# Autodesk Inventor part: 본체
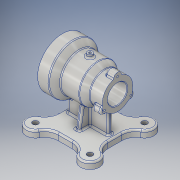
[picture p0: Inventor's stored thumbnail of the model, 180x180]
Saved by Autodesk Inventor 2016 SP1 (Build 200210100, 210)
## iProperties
Created: 2017-03
Part Number: 본체
Material: 알루미늄 6061
Document SubType Name: Modeling
Designer: Administrator
Density: 2.7 g/cm^3
Appearance: 알루미늄 - 평지
Mass: 958.762 g
Surface Area: 833.206 cm^2
Volume: 355.097 cm^3
Author: Administrator
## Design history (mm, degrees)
sketch "스케치1"
  geometry: L1 (45, 45)-(-45, 45); L2 (-45, 45)-(-45, -45); L3 (-45, -45)-(45, -45); L4 (45, -45)-(45, 45); L5 (45, 45)-(-45, -45); L6 (-45, 45)-(45, -45); C1 r 70 at (0, 0); 1 further point
  constraints: 12 end point, 4 midpoint, 2 parallel, 1 centre point, 1 horizontal, 1 perpendicular
  dimensions: "d0" = 90 distance of L3.end L2.end; "d1" = 90 distance of L2.end L1.end; "d2" = 140 diameter of C1
extrude "돌출1" new body sketch "스케치1" distance "d3" = 12; taper "d4" = 0 deg
sketch "스케치5"
  geometry: L1 (0, 0)-(49.497, -49.497); L2 (0, 0)-(49.497, 49.497); L3 (70, 0)-(-70, 0); L4 (0, -70)-(0, 70); C1 r 17 at (49.497, -49.497); C2 r 17 at (-49.497, -49.497); C3 r 17 at (49.497, 49.497); C4 r 17 at (-49.497, 49.497); A1 r 70 centre (0, 0) between (49.497, -49.497) and (49.497, 49.497); 1 further point
  constraints: 8 end point, 6 point on circle, 5 centre point, 3 symmetric about line, 2 coincident, 1 horizontal, 1 vertical, 3 other
  dimensions: "d14" = 140 diameter of A1; "d15" = 45 deg angle of L3 L1; "d16" = 45 deg angle of L2 L3; "d17" = 17 radius of C1
extrude "돌출2" join sketch "스케치5" distance "d19" = 12; taper "d20" = 0 deg
fillet "모깎기1" dims "d21" = 25
sketch "스케치6"
  geometry: L1 (45, -12.842)-(45, 12.842) reference; L2 (12.842, 45)-(-12.842, 45) reference; L3 (-45, 12.842)-(-45, -12.842) reference; L4 (-12.842, -45)-(12.842, -45) reference; C1 r 5 at (49.497, 49.497); C2 r 5 at (49.497, -49.497); C3 r 5 at (-49.497, -49.497); C4 r 5 at (-49.497, 49.497); A1 r 25 centre (70, 12.842) between (57.796, 34.661) and (45, 12.842) reference; A2 r 17 centre (49.497, 49.497) between (57.796, 34.661) and (34.661, 57.796) reference; A3 r 25 centre (12.842, 70) between (12.842, 45) and (34.661, 57.796) reference; A4 r 25 centre (-12.842, 70) between (-34.661, 57.796) and (-12.842, 45) reference; A5 r 17 centre (-49.497, 49.497) between (-34.661, 57.796) and (-57.796, 34.661) reference; A6 r 25 centre (-70, 12.842) between (-45, 12.842) and (-57.796, 34.661) reference; A7 r 25 centre (-70, -12.842) between (-57.796, -34.661) and (-45, -12.842) reference; A8 r 17 centre (-49.497, -49.497) between (-57.796, -34.661) and (-34.661, -57.796) reference; A9 r 25 centre (-12.842, -70) between (-12.842, -45) and (-34.661, -57.796) reference; A10 r 25 centre (12.842, -70) between (34.661, -57.796) and (12.842, -45) reference; A11 r 17 centre (49.497, -49.497) between (34.661, -57.796) and (57.796, -34.661) reference; A12 r 25 centre (70, -12.842) between (45, -12.842) and (57.796, -34.661) reference; 1 further point
  constraints: 4 centre point, 4 coincident, 3 equal radius
  dimensions: "d22" = 10 diameter of C1
extrude "돌출3" cut sketch "스케치6" stored distance "d23" = 12; taper "d24" = 0 deg
fillet "모깎기2" dims "d25" = 3
sketch "스케치7"
  geometry: L1 (-50, 82)-(50, 82); L2 (12.842, 0)-(-12.842, 0) reference; L3 (27, 109.5)-(15, 116.599); L4 (15, 116.599)-(9.806, 116.599); L5 (9.806, 116.599)-(-19, 116.599); L6 (-19, 116.599)-(-30, 127); L7 (-30, 127)-(-50, 127); L8 (-50, 127)-(-50, 82); L9 (27, 109.5)-(50, 109.5); L10 (50, 109.5)-(50, 82); 2 further points
  constraints: 18 end point, 3 horizontal, 2 perpendicular, 1 midpoint, 1 parallel, 1 vertical alignment
  dimensions: "d26" = 100 distance of L1.start L1.end; "d27" = 82 distance between parallel lines of L2 L1; "d28" = 90 diameter of L7 L1; "d29" = 20 distance of L6.end L7.end; "d30" = 31 horizontal distance of L5.end L7.end; "d31" = 65 horizontal distance of L3.end L7.end; "d62" = 23 distance of L3.start L9.end; "d63" = 55 diameter of L9 L1
revolve "회전1" sketch "스케치7" stored, may be unused: angle "d33" = 90 deg
sketch "스케치8"
  geometry: L1 (-50, 37)-(-50, 127) reference; L2 (-30, 37)-(-30, 127) reference; L3 (37.9, 47.401)-(37.9, 116.599) reference; L4 (50, 47.401)-(50, 116.599) reference; L5 (-19, 47.401)-(-19, 116.599) reference; L6 (15, 47.401)-(15, 116.599) reference; L7 (-50, 37)-(-50, 127) reference; L8 (-50, 82)-(50, 82); L9 (50, 47.401)-(50, 116.599) reference; L10 (50, 82)-(50, 99.5); L11 (20, 99.5)-(20, 108); L12 (50, 99.5)-(20, 99.5); L13 (20, 108)-(-27, 108); L14 (-27, 108)-(-27, 117); L15 (-27, 117)-(-50, 117); L16 (-50, 117)-(-50, 82); 1 further point
  constraints: 16 end point, 4 perpendicular, 2 midpoint, 2 point on line, 1 horizontal, 1 vertical
  dimensions: "d34" = 70 diameter of L15 L8; "d35" = 52 diameter of L13 L8; "d36" = 35 diameter of L12 L8; "d37" = 30 distance of L10.end L11.start; "d39" = 23 distance of L14.end L15.end; "d40" = 47 distance of L11.end L13.end (derived)
revolve "회전2" sketch "스케치8" stored, may be unused: angle "d41" = 90 deg
fillet "모깎기3" dims "d42" = 3
chamfer "모따기1" distance "d43" = 1; stored, may be unused: second distance "d44" = 2, angle "d45" = 45 deg
sketch "스케치9" dims "d46" = 80
  geometry: L1 (0, 0)-(-56.331, 0); C1 r 45 at (0, 0) reference; C2 r 36 at (0, 0) reference; 2 further points
  constraints: 2 end point, 1 coincident, 1 horizontal, 1 vertical alignment, 2 other
hole "구멍1" sketch "스케치9" at (0, 40) diameter "d47" = 3.242; stored, may be unused: countersink angle "d51" = 90 deg, drill point angle "d53" = 118 deg; dims "d48" = 9, "d49" = 4, "d50" = 2, "d52" = 11
sketch "스케치11" dims "d64" = 55
  geometry: L1 (0, 0)-(-49.31, -28.469); L2 (0, 0)-(0, 57.212); L3 (0, 0)-(47.893, -27.651); C1 r 7 at (0, 27.5); C2 r 29 at (0, 0) reference; C3 r 27.5 at (0, 0) reference; C4 r 26 at (0, 0) reference; C5 r 7 at (23.816, -13.75); C6 r 7 at (-23.816, -13.75); A1 r 27.5 centre (0, 0) between (23.816, -13.75) and (-23.816, -13.75) reference; 3 further points
  constraints: 6 end point, 3 centre point, 2 point on circle, 2 point on line, 1 coincident, 1 vertical, 1 vertical alignment, 2 other
  dimensions: "d65" = 7 radius of C1; "d71" = 120 deg angle of L1 L2; "d72" = 120 deg angle of L3 L2; "d73" = 7 radius of C5; "d74" = 7 radius of C6
extrude "돌출4" join sketch "스케치11" distance "d69" = 15; taper "d70" = 0 deg
sketch "스케치13"
  geometry: C1 r 17.5 at (0, -27.5) reference; A1 r 27.5 centre (0, -27.5) between (-19.573, -46.817) and (19.573, -46.817) reference; A2 r 7 centre (23.816, -41.25) between (19.573, -46.817) and (26.516, -34.792) reference; A3 r 27.5 centre (0, -27.5) between (26.516, -34.792) and (6.943, -0.891) reference; A4 r 7 centre (0, 0) between (6.943, -0.891) and (-6.943, -0.891) reference; A5 r 27.5 centre (0, -27.5) between (-6.943, -0.891) and (-26.516, -34.792) reference; A6 r 7 centre (-23.816, -41.25) between (-26.516, -34.792) and (-19.573, -46.817) reference; 2 further points
  constraints: 1 coincident
hole "구멍2" sketch "스케치13" at (0, 0) diameter "d75" = 3.242; stored, may be unused: countersink angle "d79" = 90 deg, drill point angle "d81" = 118 deg; dims "d76" = 9, "d77" = 4, "d78" = 2, "d80" = 11
sketch "스케치15"
  geometry: L1 (-37, -4)-(37, -4); L2 (37, -4)-(37, 4); L3 (37, 4)-(-37, 4); L4 (-37, 4)-(-37, -4); L5 (-37, -4)-(37, 4); L6 (37, -4)-(-37, 4); 1 further point
  constraints: 12 end point, 2 midpoint, 2 parallel, 1 horizontal, 1 perpendicular
  dimensions: "d85" = 74 distance of L3.end L2.end; "d86" = 8 distance of L1.end L2.end
extrude "돌출5" join sketch "스케치15" stored distance "d87" = 15; taper "d88" = 0 deg
sketch "스케치16"
  geometry: L1 (12, 12.842)-(12, 37.279) reference; L2 (9, -12.842)-(12, -12.842) reference; L3 (12, -12.842)-(12, -37.279) reference; L4 (9, -34.661)-(9, -12.842) reference; L5 (51.554, -16.434)-(12, -23.409); A1 r 34.599 centre (82, 0) between (47.633, -4) and (47.633, 4) reference; 2 further points; 1 other entity
  constraints: 2 end point, 1 point on circle, 1 point on line, 1 other
  dimensions: "d89" = 100 deg angle of L3 L5
feature "리브1" sketch "스케치16" dims "d90" = 1, "d91" = 8, "d92" = 0, "d93" = 0, "d94" = 1, "d95" = 1
fillet "모깎기4" dims "d96" = 3
node "작업 평면1"
sketch "스케치17"
  geometry: C1 r 5 at (0, 0); 1 further point
  constraints: 1 centre point, 1 coincident
  dimensions: "d99" = 10 diameter of C1
extrude "돌출6" join sketch "스케치17" stored distance "d100" = 15; taper "d101" = 0 deg
sketch "스케치18"
  geometry: 2 further points
  constraints: 1 coincident
hole "구멍3" sketch "스케치18" at (0, 0) diameter "d102" = 4.134; stored, may be unused: countersink angle "d106" = 90 deg, drill point angle "d108" = 118 deg; dims "d103" = 10, "d104" = 4, "d105" = 2, "d107" = 14.2
fillet "모깎기6" dims "d109" = 3
fillet "모깎기7" dims "d110" = 3
fillet "모깎기8" dims "d111" = 1
fillet "모깎기9" dims "d112" = 3
fillet "모깎기10" dims "d113" = 3
fillet "모깎기11" dims "d114" = 3
fillet "모깎기12" dims "d115" = 3
chamfer "모따기2" distance "d116" = 1; stored, may be unused: second distance "d117" = 2, angle "d118" = 45 deg
fillet "모깎기13" dims "d119" = 3
node "솔리드1"
pattern_circular "원형 패턴1" dims angle "d55" = 360 deg
pattern_circular "원형 패턴2" dims angle "d83" = 360 deg
mirror "대칭1"
node "투영된 루프2"
node "투영된 루프3"
node "투영된 루프4"
node "투영된 루프5"
node "투영된 루프6"
node "투영된 루프9"
node "투영된 루프10"
other parameters: "d98" = 122
